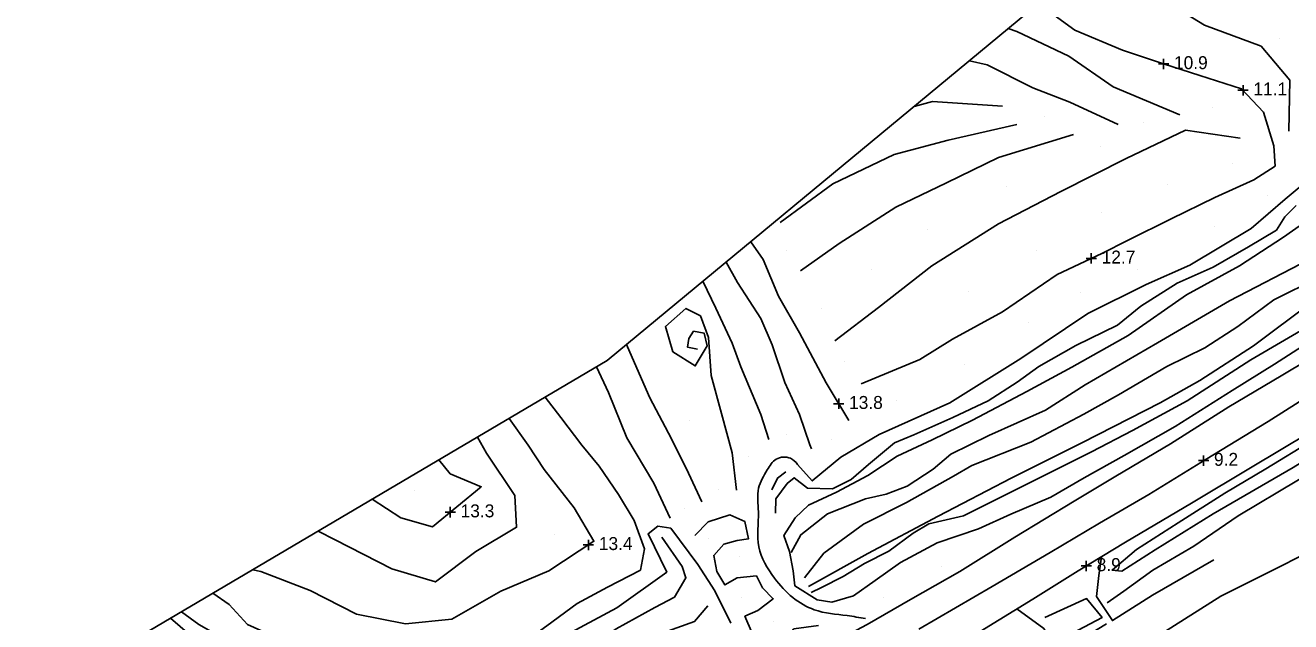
# Model space of a CAD drawing. Extents: x 2316231 to 2323598, y 363169 to 371906.
# Drawn here: x 2318819.2 to 2319307.8, y 369460.8 to 369691 of the extents above; entities that cross this region are included whole.
import ezdxf

# ---------------------------------------------------------------- set-up
doc = ezdxf.new("R2010")
doc.units = 0
for name, color, linetype in [('RD_DTM_BkLn1', 7, 'Continuous'), ('RD_DTM_Spot', 7, 'Continuous'), ('RD_DTM_TinHull', 7, 'Continuous'), ('RD_DTM_Void', 7, 'Continuous'), ('RD_EX_H2O', 7, 'Continuous'), ('RD_EX_Road', 7, 'Continuous')]:
    doc.layers.add(name, color=color, linetype=linetype)

msp = doc.modelspace()

# ---------------------------------------------------------------- linework, layer by layer
at = {"layer": 'RD_DTM_BkLn1'}
for points in [[(2319307.012, 369650.141), (2319307.366, 369669.847), (2319296.358, 369683.047), (2319274.437, 369691.149), (2319255.959, 369702.55), (2319239.539, 369708.008), (2319231.092, 369713.317), (2319229.421, 369715.263)], [(2319141.949, 369552.579), (2319164.559, 369562.021), (2319177.194, 369569.893), (2319196.48, 369580.439), (2319217.552, 369594.772), (2319234.832, 369603.001), (2319244.981, 369608.104), (2319261.557, 369616.384), (2319278.503, 369624.567), (2319293.591, 369631.364), (2319301.76, 369636.692), (2319301.241, 369644.537), (2319297.203, 369657.546), (2319288.799, 369666.579), (2319272.651, 369671.689), (2319258.685, 369676.131), (2319242.837, 369681.491), (2319224.423, 369689.144), (2319212.139, 369698.09), (2319210.3, 369699.428)], [(2319264.932, 369656.427), (2319239.169, 369667.281), (2319222.055, 369679.177), (2319201.991, 369688.689), (2319198.698, 369689.82)], [(2319241.146, 369652.72), (2319222.438, 369661.365), (2319208.167, 369666.919), (2319190.512, 369675.834), (2319183.685, 369677.387)], [(2319162.346, 369659.716), (2319169.44, 369661.668), (2319196.48, 369659.831)], [(2319110.632, 369614.97), (2319131.039, 369629.784), (2319154.639, 369641.215), (2319175.521, 369646.655), (2319202.053, 369652.723)], [(2319131.747, 369569.272), (2319148.657, 369582.123), (2319169.261, 369598.153), (2319194.915, 369614.384), (2319219.022, 369626.874), (2319244.288, 369639.585), (2319267.204, 369650.53), (2319288.293, 369647.494)], [(2319118.448, 369596.284), (2319133.389, 369606.853), (2319155.331, 369620.811), (2319174.838, 369630.27), (2319194.967, 369640.059), (2319223.925, 369648.919)], [(2319120.02, 369477.707), (2319127.567, 369487.229), (2319142.857, 369498.405), (2319159.362, 369506.829), (2319177.632, 369516.986), (2319184.66, 369521.079), (2319207.411, 369530.091), (2319227.869, 369540.954), (2319241.253, 369548.427), (2319259.956, 369559.37), (2319274.569, 369566.515), (2319287.36, 369574.708), (2319301.238, 369585.116), (2319318.388, 369593.501), (2319332.76, 369602.592), (2319342.833, 369606.92), (2319357.171, 369616.179), (2319376.192, 369626.417), (2319394.142, 369637.101), (2319407.081, 369643.825), (2319414.766, 369645.706), (2319418.435, 369644.267)], [(2319419.456, 369640.883), (2319417.506, 369635.51), (2319408.655, 369629.898), (2319397.426, 369623.798), (2319386.563, 369616.848), (2319377.239, 369612.159), (2319364.523, 369604.777), (2319350.817, 369595.085), (2319339.799, 369588.339), (2319332.395, 369585.525), (2319318.385, 369577.087), (2319292.426, 369561.945), (2319267.789, 369546.115), (2319246.719, 369534.588), (2319230.812, 369526.339), (2319209.209, 369515.507), (2319181.407, 369501.675), (2319167.985, 369498.559), (2319161.938, 369495.01), (2319152.627, 369488.076), (2319143.147, 369483.231), (2319134.932, 369478.201), (2319126.578, 369474.032), (2319122.557, 369472.036)], [(2319384.688, 369637.079), (2319378.929, 369633.934), (2319370.35, 369630.005), (2319356.679, 369622.485), (2319339.762, 369615.352), (2319314.844, 369600.669), (2319284.154, 369584.728), (2319256.292, 369568.462), (2319228.381, 369552.184), (2319213.111, 369542.452), (2319191.274, 369532.623), (2319176.542, 369525.455), (2319169.744, 369519.737), (2319159.742, 369513.177), (2319151.596, 369509.997), (2319143.637, 369508.189), (2319128.889, 369502.453), (2319118.628, 369494.378), (2319114.867, 369487.451)], [(2319108.824, 369502.702), (2319109.032, 369508.168), (2319113.396, 369514.113), (2319116.07, 369516.355), (2319121.217, 369512.282), (2319130.849, 369512.064), (2319138.054, 369515.726), (2319144.721, 369521.469), (2319154.733, 369529.879), (2319162.233, 369532.872), (2319177.345, 369539.62), (2319190.915, 369546.066), (2319202.21, 369553.324), (2319210.525, 369559.261), (2319224.761, 369567.422), (2319240.953, 369575.275), (2319249.873, 369582.593), (2319263.933, 369591.46), (2319277.8, 369597.618), (2319291.521, 369605.483), (2319302.323, 369611.992), (2319305.548, 369617.06), (2319309.857, 369621.526)], [(2319317.73, 369570.609), (2319301.501, 369560.202), (2319285.118, 369550.094), (2319263.116, 369536.113), (2319243.457, 369524.912), (2319228.061, 369516.315), (2319215.154, 369508.875), (2319199.661, 369502.283), (2319187.181, 369496.596), (2319171.325, 369491.296), (2319157.044, 369483.683), (2319147.374, 369476.632), (2319138.916, 369470.792), (2319130.535, 369468.269), (2319124.905, 369469.17), (2319116.352, 369474.623), (2319115.63, 369480.368), (2319114.273, 369487.931), (2319112.121, 369494.126), (2319116.49, 369500.895), (2319121.648, 369505.75), (2319132.37, 369510.779), (2319144.52, 369517.256), (2319155.792, 369524.717), (2319169.397, 369531.043), (2319184.907, 369538.554), (2319205.867, 369549.7), (2319223.32, 369559.062), (2319245.05, 369571.242), (2319267.586, 369586.952), (2319287.997, 369598.161), (2319305.006, 369609.196), (2319316.64, 369617.467)], [(2319137.183, 369538.483), (2319128.355, 369552.973), (2319118.095, 369572.305), (2319110.017, 369586.409), (2319104.027, 369600.574), (2319099.299, 369607.504)], [(2319122.706, 369527.517), (2319122.141, 369529.12), (2319118.132, 369540.779), (2319112.432, 369553.104), (2319107.506, 369567.621), (2319103.168, 369577.898), (2319094.121, 369591.792), (2319089.775, 369599.616)], [(2319106.252, 369531.089), (2319103.163, 369540.774), (2319095.477, 369559.162), (2319092.148, 369568.359), (2319085.784, 369581.785), (2319080.825, 369592.205)], [(2319093.746, 369511.507), (2319092.068, 369525.995), (2319087.97, 369541.224), (2319083.989, 369555.868), (2319082.979, 369570.496), (2319079.836, 369578.845), (2319074.265, 369581.751), (2319066.338, 369574.726), (2319069.223, 369565.042), (2319077.837, 369559.541), (2319082.437, 369567.312), (2319081.305, 369572.14), (2319077.215, 369572.926), (2319075.362, 369570.178), (2319074.831, 369566.791), (2319078.742, 369565.958)], [(2319080.414, 369507.125), (2319075.255, 369518.134), (2319068.748, 369531.406), (2319060.356, 369547.171), (2319053.526, 369562.761), (2319051.34, 369567.787)], [(2319068.169, 369500.779), (2319061.878, 369514.337), (2319051.501, 369531.783), (2319044.384, 369549.32), (2319039.768, 369559.181)], [(2319322.975, 369553.297), (2319299.033, 369538.072), (2319274.747, 369523.339), (2319252.987, 369509.905), (2319233.938, 369498.88), (2319214.935, 369487.569), (2319192.459, 369474.329), (2319164.13, 369457.898)], [(2318891.621, 369471.802), (2318897.917, 369467.464), (2318904.955, 369459.752), (2318913.827, 369455.718), (2318926.25, 369450.52), (2318936.217, 369445.944), (2318945.062, 369439.117), (2318957.391, 369436.462), (2318967.14, 369435.873), (2318985.075, 369437.068), (2318996.214, 369444.112), (2319009.334, 369451.145), (2319020.537, 369459.203), (2319032.304, 369467.843), (2319044.036, 369474.132), (2319056.664, 369480.726), (2319058.211, 369488.931), (2319054.234, 369499.886), (2319048.271, 369509.92), (2319040.725, 369520.894), (2319034.058, 369528.903), (2319025.997, 369539.605), (2319019.896, 369547.461)], [(2318906.999, 369480.872), (2318910.124, 369480.125), (2318929.149, 369472.863), (2318947.029, 369463.637), (2318966.049, 369460.003), (2318983.881, 369461.819), (2319002.845, 369472.594), (2319021.377, 369480.446), (2319038.757, 369491.85), (2319031.09, 369504.735), (2319019.542, 369519.597), (2319013.288, 369528.905), (2319006.059, 369539.299)], [(2319242.554, 369480.345), (2319238.796, 369480.699), (2319248.208, 369488.683), (2319264.33, 369499.019), (2319282.319, 369510.371), (2319298.221, 369519.825), (2319316.339, 369530.927), (2319333.469, 369540.064), (2319340.465, 369542.581), (2319343.54, 369541.515), (2319345.337, 369538.354), (2319344.507, 369534.729), (2319331.484, 369528.006), (2319310.827, 369515.557), (2319287.43, 369501.666), (2319270.322, 369489.891), (2319254.504, 369480.628), (2319243.313, 369472.641), (2319236.963, 369468.031)], [(2319204.67, 369424.274), (2319230.331, 369441.781), (2319259.095, 369456.897), (2319280.809, 369470.677), (2319333.673, 369497.15), (2319356.665, 369511.126), (2319383.235, 369528.879), (2319401.195, 369536.997), (2319415.052, 369518.518)], [(2318932.299, 369495.794), (2318938.801, 369492.388), (2318960.742, 369481.219), (2318977.558, 369476.153), (2318993.198, 369487.936), (2319008.872, 369497.284), (2319008.22, 369509.558), (2318997.229, 369525.814), (2318993.788, 369532.062)], [(2318953.171, 369508.105), (2318964.199, 369500.837), (2318976.417, 369497.454), (2318995.251, 369512.921), (2318983.281, 369517.914), (2318978.858, 369523.256)], [(2319107.367, 369511.686), (2319109.599, 369516.21), (2319112.835, 369518.64)], [(2319125.391, 369459.272), (2319115.978, 369458.056), (2319112.351, 369453.802), (2319108.143, 369450.482), (2319099.951, 369447.481), (2319099.783, 369456.363), (2319097.06, 369462.895), (2319102.025, 369465.065), (2319107.993, 369469.629), (2319103.802, 369473.841), (2319101.463, 369478.509), (2319094.106, 369477.712), (2319089.293, 369475.004), (2319086.18, 369480.129), (2319085.007, 369486.354), (2319088.862, 369490.703), (2319094.026, 369492.132), (2319098.47, 369492.813), (2319097.013, 369499.41), (2319091.154, 369502.031), (2319082.879, 369499.341), (2319077.719, 369494.104)], [(2318875.302, 369462.177), (2318882.66, 369455.739), (2318895.145, 369448.81), (2318912.61, 369435.504), (2318932.986, 369424.021), (2318946.156, 369417.935), (2318956.539, 369415.326), (2318965.793, 369415.755), (2318977.806, 369416.658), (2318989.335, 369420.835), (2319001.79, 369428.648), (2319016.482, 369439.481), (2319033.971, 369448.855), (2319047.293, 369458.072), (2319062.222, 369466.265), (2319069.895, 369470.319), (2319074.279, 369477.769), (2319072.762, 369482.086), (2319064.895, 369493.396)], [(2319212.796, 369462.357), (2319228.962, 369469.709), (2319234.952, 369462.444), (2319218.576, 369453.768), (2319221.545, 369450.816), (2319236.681, 369459.928)], [(2319082.673, 369466.969), (2319077.592, 369460.908), (2319065.788, 369456.566)]]:
    msp.add_lwpolyline(points, dxfattribs=at)
at = {"layer": 'RD_DTM_Spot'}
for p, q in [((2319303.465, 369686.09), (2319303.465, 369686.09)), ((2319212.872, 369655.781), (2319212.872, 369655.781)), ((2319277.552, 369659.285), (2319277.552, 369659.285)), ((2319250.902, 369653.421), (2319250.902, 369653.421)), ((2319234.297, 369644.138), (2319234.297, 369644.138)), ((2319285.34, 369637.65), (2319285.34, 369637.65)), ((2319197.952, 369628.823), (2319197.952, 369628.823)), ((2319260.386, 369629.581), (2319260.386, 369629.581)), ((2319298.764, 369625.38), (2319298.764, 369625.38)), ((2319234.641, 369618.794), (2319234.641, 369618.794)), ((2319167.713, 369612.354), (2319167.713, 369612.354)), ((2319278.181, 369613.336), (2319278.181, 369613.336)), ((2319112.915, 369604.06), (2319112.915, 369604.06)), ((2319209.531, 369603.957), (2319209.531, 369603.957)), ((2319145.882, 369596.892), (2319145.882, 369596.892)), ((2319248.658, 369596.84), (2319248.658, 369596.84)), ((2319183.294, 369588.208), (2319183.294, 369588.208)), ((2319226.575, 369587.825), (2319226.575, 369587.825)), ((2319126.489, 369581.738), (2319126.489, 369581.738)), ((2319206.484, 369576.232), (2319206.484, 369576.232)), ((2319135.571, 369561.064), (2319135.571, 369561.064)), ((2319181.977, 369560.187), (2319181.977, 369560.187)), ((2319155.5, 369546.348), (2319155.5, 369546.348)), ((2319075.745, 369538.603), (2319075.745, 369538.603)), ((2319113.221, 369532.986), (2319113.221, 369532.986)), ((2319130.46, 369531.081), (2319130.46, 369531.081)), ((2319098.398, 369524.482), (2319098.398, 369524.482)), ((2318969.388, 369511.457), (2318969.388, 369511.457)), ((2319086.789, 369511.83), (2319086.789, 369511.83)), ((2319073.8, 369504.665), (2319073.8, 369504.665)), ((2319023.444, 369494.497), (2319023.444, 369494.497)), ((2319047.734, 369489.678), (2319047.734, 369489.678)), ((2319083.108, 369492.822), (2319083.108, 369492.822)), ((2319094.996, 369485.824), (2319094.996, 369485.824)), ((2319172.936, 369482.143), (2319172.936, 369482.143)), ((2319095.618, 369470.244), (2319095.618, 369470.244)), ((2319150.717, 369469.977), (2319150.717, 369469.977)), ((2319107.924, 369460.975), (2319107.924, 369460.975))]:
    msp.add_line(p, q, dxfattribs=at)
at = {"layer": 'RD_DTM_TinHull'}
msp.add_lwpolyline([(2318500.627, 367718.473), (2317350.395, 369314.708), (2317732.783, 369650.329), (2318062.064, 369676.571), (2318100.376, 368980.922), (2318611.552, 369306.612), (2319043.87, 369561.601), (2319323.163, 369792.894), (2318905.258, 370457.792), (2319170.205, 370651.465)], dxfattribs=at)
at = {"layer": 'RD_DTM_Void'}
for p, q in [((2319256.709, 369676.119), (2319260.709, 369676.119)), ((2319258.709, 369674.119), (2319258.709, 369678.119)), ((2319287.369, 369665.966), (2319291.369, 369665.966)), ((2319289.369, 369663.966), (2319289.369, 369667.966)), ((2319230.779, 369599.07), (2319230.779, 369603.07)), ((2319228.779, 369601.07), (2319232.779, 369601.07)), ((2319131.251, 369544.936), (2319135.251, 369544.936)), ((2319133.251, 369542.936), (2319133.251, 369546.936)), ((2319274.145, 369520.967), (2319274.145, 369524.967)), ((2319272.145, 369522.967), (2319276.145, 369522.967)), ((2318983.267, 369501.08), (2318983.267, 369505.08)), ((2318981.267, 369503.08), (2318985.267, 369503.08)), ((2319034.634, 369490.457), (2319038.634, 369490.457)), ((2319036.634, 369488.457), (2319036.634, 369492.457)), ((2319228.856, 369480.335), (2319228.856, 369484.335)), ((2319226.856, 369482.335), (2319230.856, 369482.335))]:
    msp.add_line(p, q, dxfattribs=at)
at = {"layer": 'RD_EX_H2O'}
for points in [[(2319121.579, 369474.428), (2319144.457, 369487.116), (2319171.713, 369501.488), (2319199.866, 369516.165), (2319227.417, 369530.01), (2319257.388, 369545.322), (2319272.652, 369553.848), (2319293.385, 369567.311), (2319315.987, 369584.095), (2319332.666, 369589.212), (2319357.029, 369602.799), (2319376.003, 369617.62), (2319394.938, 369629.553), (2319407.244, 369636.34), (2319416.686, 369640.79), (2319418.939, 369642.473)], [(2319242.554, 369480.345), (2319255.381, 369488.478), (2319277.848, 369502.397), (2319308.716, 369520.379), (2319328.644, 369532.676), (2319342.639, 369540.493)]]:
    msp.add_lwpolyline(points, dxfattribs=at)
at = {"layer": 'RD_EX_Road'}
for points in [[(2319117.398, 369521.541), (2319123.035, 369515.125), (2319134.101, 369524.342), (2319148.876, 369533.014), (2319176.133, 369545.308), (2319203.523, 369562.401), (2319229.493, 369579.74), (2319251.97, 369590.997), (2319268.792, 369598.405), (2319292.561, 369612.533), (2319305.656, 369623.899), (2319318.796, 369634.824), (2319326.686, 369648.283), (2319338.715, 369663.666), (2319326.438, 369685.145), (2319308.292, 369709.723), (2319294.391, 369728.86), (2319284.919, 369741.312), (2319275.829, 369753.695)], [(2318803.058, 369252.516), (2318828.743, 369267.803), (2318853.592, 369283.07), (2318878.253, 369298.757), (2318904.128, 369313.864), (2318922.404, 369325.466), (2318959.668, 369347.58), (2318993.223, 369367.959), (2319023.171, 369385.897), (2319061.963, 369410.247), (2319089.625, 369427.088), (2319105.937, 369437.363), (2319120.966, 369446.404), (2319130.451, 369452.406), (2319144.193, 369459.686), (2319161.027, 369469.338), (2319180.064, 369480.136), (2319201.214, 369493.37), (2319224.218, 369507.263), (2319240.288, 369516.967), (2319261.375, 369529.521), (2319283.879, 369543.691), (2319304.08, 369555.736), (2319325.837, 369568.704)], [(2319314.575, 369533.634), (2319292.877, 369520.522), (2319269.466, 369506.548), (2319243.95, 369491.45), (2319225.688, 369480.421), (2319208.179, 369469.532), (2319187.808, 369456.962)], [(2319091.603, 369460.285), (2319085.437, 369472.72), (2319078.794, 369482.914), (2319068.387, 369496.946), (2319063.437, 369497.617), (2319059.638, 369494.748), (2319066.83, 369479.933), (2319047.646, 369466.079), (2319020.952, 369451.884), (2318993.853, 369433.381), (2318981.538, 369427.179), (2318958.647, 369425.7), (2318947.515, 369428.993), (2318933.726, 369433.184), (2318919.615, 369439.585), (2318910.655, 369444.944), (2318899.531, 369452.057), (2318886.167, 369459.767), (2318879.501, 369464.653)], [(2319234.704, 369485.867), (2319233.64, 369478.625), (2319232.845, 369470.512), (2319238.944, 369461.205), (2319254.358, 369470.996), (2319278.077, 369484.694)], [(2319201.96, 369465.695), (2319212.416, 369458.11), (2319217.956, 369449.283), (2319200.66, 369437.974), (2319193.494, 369432.688), (2319201.329, 369420.042), (2319211.025, 369404.831), (2319220.859, 369388.461), (2319238.453, 369358.766), (2319246.799, 369343.395), (2319252.689, 369333.893)]]:
    msp.add_lwpolyline(points, dxfattribs=at)
msp.add_spline([(2319143.573, 369461.993), (2319136.488, 369463.129), (2319123.823, 369465.404), (2319115.516, 369470.139), (2319108.489, 369477.636), (2319102.369, 369489.665), (2319102.238, 369503.226), (2319102.31, 369512.393), (2319105.665, 369519.382), (2319109.089, 369523.518), (2319114.629, 369523.871), (2319117.398, 369521.541)], degree=3, dxfattribs=at)

# ---------------------------------------------------------------- texts
at = {"layer": 'RD_DTM_Void'}
for s, p in [('10.9', (2319262.709, 369674.119)), ('11.1', (2319293.369, 369663.966)), ('12.7', (2319234.779, 369599.07)), ('13.8', (2319137.251, 369542.936)), ('9.2', (2319278.145, 369520.967)), ('13.3', (2318987.267, 369501.08)), ('13.4', (2319040.634, 369488.457)), ('8.9', (2319232.856, 369480.335))]:
    msp.add_text(s, height=5, dxfattribs=at).set_placement(p)

doc.saveas('drawing.dxf')
